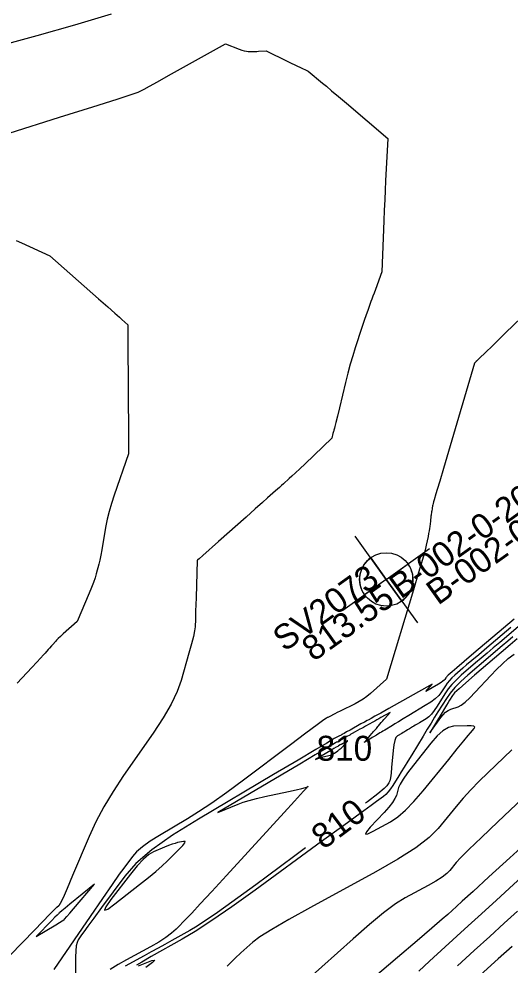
# Model space of a CAD drawing. Extents: x 2079879 to 2092887, y 778083 to 784051.
# Drawn here: x 2084197.8 to 2084253, y 781032.2 to 781138.5 of the extents above; entities that cross this region are included whole.
import ezdxf

# ---------------------------------------------------------------- set-up
doc = ezdxf.new("R2010")
doc.units = 0
for name, color, linetype in [('DT_X_Contour_Major', 7, 'Continuous'), ('DT_X_Contour_Minor', 7, 'Continuous'), ('GT_Project_Soil_Boring', 7, 'Continuous'), ('GT_Project_Text', 7, 'Continuous'), ('SV_X_Text_Comment', 7, 'Continuous'), ('SV_X_Text_Elevation', 7, 'Continuous'), ('SV_X_Text_Name', 7, 'Continuous')]:
    doc.layers.add(name, color=color, linetype=linetype)

msp = doc.modelspace()

# ---------------------------------------------------------------- linework, layer by layer
at = {"layer": 'DT_X_Contour_Major'}
for points in [[(2084197.55, 781113.57), (2084198.15, 781113.29), (2084201.33, 781111.82), (2084206.78, 781107.01), (2084207.82, 781106.09), (2084208.61, 781105.4), (2084209.13, 781104.93), (2084209.41, 781104.69), (2084210.08, 781104.1), (2084210.13, 781094.98), (2084210.14, 781093.24), (2084210.15, 781091.93), (2084210.15, 781091.06), (2084210.15, 781090.63), (2084210.14, 781089.61), (2084208.54, 781084.97), (2084208.23, 781084), (2084207.97, 781083.1), (2084207.76, 781082.27), (2084207.61, 781081.49), (2084207.28, 781079.52), (2084207.16, 781078.82), (2084207.05, 781078.2), (2084206.93, 781077.66), (2084206.82, 781077.21), (2084206.54, 781076.11), (2084206.41, 781075.66), (2084206.24, 781075.15), (2084206.01, 781074.57), (2084205.74, 781073.93), (2084204.38, 781070.77), (2084202.83, 781069.36), (2084202.52, 781069.08), (2084202.27, 781068.84), (2084202.08, 781068.65), (2084201.94, 781068.5), (2084201.64, 781068.16), (2084201.52, 781068.03), (2084201.28, 781067.76), (2084201.15, 781067.61), (2084200.79, 781067.22), (2084200.6, 781067), (2084200.28, 781066.66), (2084199.85, 781066.19), (2084199.29, 781065.6), (2084197.65, 781063.83)], [(2084253.92, 781070.15), (2084251.88, 781068.42), (2084251.14, 781067.79), (2084250.44, 781067.2), (2084249.78, 781066.63), (2084249.16, 781066.1), (2084247.55, 781064.74), (2084246.99, 781064.22), (2084246.49, 781063.7), (2084246.06, 781063.18), (2084245.7, 781062.65), (2084244.82, 781061.24), (2084244.5, 781060.75), (2084244.19, 781060.36), (2084243.89, 781060.05), (2084243.6, 781059.84), (2084242.84, 781059.38), (2084242.58, 781059.23), (2084242.37, 781059.1), (2084242.2, 781059), (2084242.08, 781058.93), (2084241.83, 781058.77), (2084241.74, 781058.72), (2084241.66, 781058.67), (2084241.58, 781058.63), (2084241.52, 781058.59), (2084241.35, 781058.49), (2084241.28, 781058.44), (2084241.17, 781058.38), (2084241.03, 781058.29), (2084240.87, 781058.19), (2084240.38, 781057.9), (2084240.21, 781057.72), (2084240.08, 781057.38), (2084239.97, 781056.89), (2084239.89, 781056.26), (2084239.72, 781054.35), (2084239.65, 781053.71), (2084239.58, 781053.21), (2084239.5, 781052.86), (2084239.42, 781052.65), (2084239.19, 781052.29), (2084238.89, 781052), (2084238.16, 781051.41), (2084237, 781050.51), (2084236.79, 781050.36)], [(2084234.05, 781056.52), (2084234.07, 781056.54), (2084234.1, 781056.57), (2084234.14, 781056.61), (2084234.17, 781056.65), (2084234.47, 781056.99), (2084234.75, 781057.31), (2084234.76, 781057.32), (2084234.76, 781057.32), (2084234.76, 781057.33), (2084234.77, 781057.33), (2084234.77, 781057.34), (2084234.79, 781057.36), (2084234.75, 781057.34), (2084234.73, 781057.33), (2084234.69, 781057.31), (2084234.63, 781057.27), (2084234.56, 781057.23), (2084234.33, 781057.1), (2084234.25, 781057.06), (2084234.19, 781057.03), (2084234.16, 781057.01), (2084234.14, 781057), (2084234.11, 781056.98), (2084234.09, 781056.97), (2084234.06, 781056.95), (2084234.01, 781056.93), (2084233.95, 781056.89), (2084233.77, 781056.79), (2084233.66, 781056.73), (2084233.48, 781056.63), (2084233.23, 781056.48), (2084232.9, 781056.28), (2084231.17, 781055.26), (2084231.6, 781055.44), (2084231.71, 781055.48), (2084231.84, 781055.52), (2084231.99, 781055.56), (2084232.16, 781055.6), (2084232.66, 781055.71), (2084232.84, 781055.75), (2084233.01, 781055.81), (2084233.16, 781055.89), (2084233.3, 781055.98), (2084233.66, 781056.24), (2084233.78, 781056.33), (2084233.87, 781056.4), (2084233.94, 781056.45), (2084233.98, 781056.47), (2084234.05, 781056.52)], [(2084264.54, 781051.3), (2084264.44, 781051.22), (2084263.52, 781050.39), (2084262.27, 781049.26), (2084260.72, 781047.85), (2084258.85, 781046.15), (2084253.43, 781041.22), (2084251.51, 781039.47), (2084249.81, 781037.92), (2084248.33, 781036.56), (2084247.06, 781035.41), (2084243.98, 781032.6), (2084242.76, 781031.5)], [(2084230.06, 781045.33), (2084228.84, 781044.42), (2084227.24, 781043.23), (2084225.77, 781042.16), (2084224.45, 781041.19), (2084221.09, 781038.75), (2084219.9, 781037.9), (2084218.82, 781037.16), (2084217.88, 781036.55), (2084217.05, 781036.06), (2084215.02, 781034.92), (2084214.25, 781034.49), (2084213.48, 781034.07), (2084212.7, 781033.64), (2084211.91, 781033.21), (2084209.8, 781032.06)]]:
    msp.add_lwpolyline(points, dxfattribs=at)
at = {"layer": 'DT_X_Contour_Minor'}
for points in [[(2084188.46, 781133.47), (2084199.89, 781136.6), (2084204.13, 781137.8), (2084208.25, 781139.04)], [(2084191.05, 781123.82), (2084202.42, 781127.4), (2084206.16, 781128.58), (2084208.88, 781129.44), (2084210.57, 781129.99), (2084211.23, 781130.22), (2084211.61, 781130.4), (2084211.91, 781130.55), (2084212.51, 781130.89), (2084213.42, 781131.39), (2084214.64, 781132.08), (2084221.04, 781135.67), (2084222.59, 781135.07), (2084222.9, 781134.95), (2084223.17, 781134.87), (2084223.4, 781134.82), (2084223.59, 781134.8), (2084224.04, 781134.79), (2084224.22, 781134.79), (2084224.39, 781134.79), (2084224.57, 781134.8), (2084224.76, 781134.81), (2084225.64, 781134.86), (2084227.99, 781133.7), (2084228.45, 781133.48), (2084228.84, 781133.29), (2084229.16, 781133.14), (2084229.4, 781133.03), (2084230.34, 781132.6), (2084231.96, 781131.25), (2084232.39, 781130.89), (2084232.98, 781130.39), (2084233.74, 781129.75), (2084234.65, 781128.97), (2084239.3, 781125), (2084239.04, 781120.25), (2084238.99, 781119.2), (2084238.94, 781118.11), (2084238.89, 781116.96), (2084238.84, 781115.76), (2084238.63, 781110.03), (2084237.89, 781108.05), (2084237.74, 781107.65), (2084237.6, 781107.29), (2084237.49, 781106.97), (2084237.39, 781106.7), (2084237.15, 781106.03), (2084237.03, 781105.7), (2084236.87, 781105.22), (2084236.65, 781104.58), (2084236.39, 781103.79), (2084235.63, 781101.49), (2084235.35, 781100.59), (2084235.07, 781099.65), (2084234.81, 781098.66), (2084234.54, 781097.61), (2084233.86, 781094.76), (2084233.63, 781093.82), (2084233.46, 781093.12), (2084233.35, 781092.67), (2084233.3, 781092.47), (2084233.24, 781092.26), (2084233.22, 781092.18), (2084233.19, 781092.09), (2084233.16, 781091.99), (2084233.13, 781091.89), (2084232.99, 781091.37), (2084229.99, 781088.48), (2084229.4, 781087.92), (2084228.91, 781087.45), (2084228.52, 781087.08), (2084228.22, 781086.82), (2084227.58, 781086.24), (2084227.34, 781086.03), (2084227.11, 781085.83), (2084226.89, 781085.63), (2084226.67, 781085.43), (2084225.77, 781084.64), (2084225.2, 781084.13), (2084224.4, 781083.42), (2084223.36, 781082.49), (2084220.26, 781079.74), (2084218.52, 781078.19), (2084218.08, 781077.8), (2084217.93, 781077.67), (2084217.92, 781077.66), (2084217.91, 781077.65), (2084217.91, 781077.65), (2084217.91, 781077.65), (2084217.9, 781077.65), (2084217.9, 781077.64), (2084217.9, 781077.64), (2084217.9, 781077.64), (2084217.89, 781077.64), (2084217.88, 781077.62), (2084217.75, 781073.47), (2084217.72, 781072.65), (2084217.7, 781071.97), (2084217.67, 781071.03), (2084217.64, 781070.16), (2084217.59, 781069.73), (2084217.46, 781069.09), (2084217.25, 781068.24), (2084216.95, 781067.19), (2084216.07, 781064.12), (2084215.62, 781062.89), (2084214.95, 781061.49), (2084214.05, 781059.94), (2084212.92, 781058.23), (2084209.6, 781053.45), (2084208.43, 781051.68), (2084207.39, 781049.95), (2084206.49, 781048.25), (2084205.73, 781046.6), (2084203.88, 781042.23), (2084203.26, 781040.78), (2084202.8, 781039.73), (2084202.49, 781039.08), (2084202.33, 781038.82), (2084202.12, 781038.64), (2084202.05, 781038.59), (2084201.97, 781038.52), (2084201.96, 781038.51), (2084201.96, 781038.51), (2084201.81, 781038.36), (2084201.37, 781037.91), (2084199.6, 781036.1), (2084194.11, 781030.46)], [(2084254.32, 781104.92), (2084252.51, 781103.17), (2084252.05, 781102.72), (2084251.61, 781102.3), (2084251.19, 781101.89), (2084250.1, 781100.84), (2084249.74, 781100.49), (2084249.48, 781100.24), (2084249.32, 781100.08), (2084249.26, 781100.02), (2084249.22, 781099.99), (2084249.21, 781099.98), (2084249.19, 781099.96), (2084249.17, 781099.94), (2084249.15, 781099.91), (2084249.02, 781099.79), (2084246.1, 781089.86), (2084245.54, 781087.96), (2084245.13, 781086.54), (2084244.84, 781085.58), (2084244.7, 781085.1), (2084244.51, 781084.43), (2084244.44, 781084.2), (2084244.39, 781084.01), (2084244.35, 781083.86), (2084244.33, 781083.75), (2084244.29, 781083.51), (2084244.27, 781083.41), (2084244.23, 781083.19), (2084244.21, 781083.07), (2084244.16, 781082.72), (2084244.13, 781082.58), (2084244.11, 781082.42), (2084244.09, 781082.23), (2084244.07, 781082.03), (2084244.01, 781081.44), (2084243.98, 781081.21), (2084243.94, 781080.94), (2084243.88, 781080.64), (2084243.81, 781080.3), (2084243.61, 781079.35), (2084243.47, 781078.77), (2084243.18, 781077.74), (2084242.74, 781076.26), (2084242.17, 781074.33), (2084239.15, 781064.28), (2084237.34, 781062.68), (2084236.94, 781062.35), (2084236.53, 781062.04), (2084236.09, 781061.77), (2084235.63, 781061.52), (2084233.95, 781060.69), (2084233.61, 781060.52), (2084233.35, 781060.39), (2084233.18, 781060.31), (2084232.84, 781060.14), (2084232.62, 781060.03), (2084232.55, 781059.99), (2084232.5, 781059.97), (2084232.39, 781059.91), (2084232.1, 781059.71), (2084231.34, 781059.14), (2084230.08, 781058.2), (2084228.35, 781056.9), (2084223.07, 781052.94), (2084221.19, 781051.55), (2084219.52, 781050.36), (2084218.04, 781049.37), (2084216.77, 781048.58), (2084213.65, 781046.74), (2084212.58, 781046.07), (2084211.72, 781045.46), (2084211.05, 781044.89), (2084210.59, 781044.38), (2084209.63, 781043.07), (2084209.12, 781042.36), (2084208.32, 781041.22), (2084207.23, 781039.64), (2084205.85, 781037.63), (2084201.77, 781031.68)], [(2084253.49, 781071.03), (2084252.29, 781070.02), (2084248.96, 781067.19), (2084247.86, 781066.26), (2084247.05, 781065.57), (2084246.53, 781065.12), (2084246.3, 781064.93), (2084246.08, 781064.74), (2084246, 781064.67), (2084245.93, 781064.59), (2084245.87, 781064.52), (2084245.82, 781064.45), (2084245.69, 781064.25), (2084245.62, 781064.16), (2084245.47, 781064.05), (2084245.27, 781063.91), (2084244.99, 781063.74), (2084243.58, 781062.88), (2084244.29, 781063.71), (2084239.41, 781060.99), (2084238.49, 781060.48), (2084237.83, 781060.11), (2084237.42, 781059.88), (2084237.28, 781059.8), (2084237.22, 781059.77), (2084237.15, 781059.73), (2084236.97, 781059.63), (2084236.68, 781059.47), (2084236.27, 781059.25), (2084235.06, 781058.57), (2084234.66, 781058.35), (2084234.38, 781058.19), (2084234.2, 781058.09), (2084234.15, 781058.06), (2084234.14, 781058.06), (2084234.14, 781058.06), (2084234.14, 781058.06), (2084234.14, 781058.06), (2084234.14, 781058.06), (2084234.14, 781058.06), (2084234.13, 781058.05), (2084234.11, 781058.04), (2084234.08, 781058.02), (2084234.04, 781058), (2084233.8, 781057.87), (2084233.27, 781057.61), (2084233.17, 781057.55), (2084233.08, 781057.51), (2084233.01, 781057.47), (2084232.97, 781057.43), (2084232.86, 781057.36), (2084232.43, 781057.1), (2084231.22, 781056.38), (2084229.23, 781055.2), (2084226.45, 781053.56), (2084218.01, 781048.57), (2084215.12, 781046.77), (2084212.77, 781045.1), (2084210.98, 781043.57), (2084209.73, 781042.17), (2084207.12, 781038.63), (2084206.25, 781037.44), (2084205.59, 781036.53), (2084205.13, 781035.91), (2084204.89, 781035.56), (2084204.51, 781035), (2084204.38, 781034.72), (2084204.29, 781034.31), (2084204.23, 781033.75), (2084204.21, 781033.05), (2084204.2, 781031)], [(2084253.1, 781070.08), (2084250.42, 781067.81), (2084249.5, 781067.02), (2084248.74, 781066.38), (2084248.15, 781065.88), (2084247.73, 781065.52), (2084246.82, 781064.74), (2084246.49, 781064.44), (2084246.21, 781064.15), (2084245.96, 781063.85), (2084245.76, 781063.55), (2084245.26, 781062.74), (2084245.01, 781062.43), (2084244.63, 781062.08), (2084244.13, 781061.71), (2084243.5, 781061.31), (2084241.65, 781060.19), (2084241.01, 781059.81), (2084240.49, 781059.5), (2084240.09, 781059.25), (2084239.8, 781059.08), (2084238.95, 781058.57), (2084238.75, 781058.45), (2084238.57, 781058.34), (2084238.41, 781058.24), (2084238.01, 781058), (2084237.7, 781057.82), (2084237.54, 781057.72), (2084237.38, 781057.63), (2084236.63, 781057.17), (2084236.96, 781057.56), (2084237.07, 781057.69), (2084237.11, 781057.73), (2084237.13, 781057.75), (2084237.16, 781057.79), (2084237.18, 781057.81), (2084237.26, 781057.9), (2084237.32, 781057.97), (2084237.5, 781058.18), (2084237.57, 781058.26), (2084237.64, 781058.35), (2084237.8, 781058.52), (2084238.01, 781058.76), (2084238.09, 781058.86), (2084238.17, 781058.95), (2084238.25, 781059.04), (2084238.56, 781059.4), (2084238.65, 781059.51), (2084238.75, 781059.62), (2084238.86, 781059.75), (2084238.97, 781059.88), (2084239.54, 781060.54), (2084238.5, 781059.96), (2084238.28, 781059.83), (2084238.05, 781059.71), (2084237.83, 781059.58), (2084237.6, 781059.45), (2084236.77, 781058.99), (2084236.56, 781058.87), (2084236.35, 781058.76), (2084236.16, 781058.65), (2084235.64, 781058.36), (2084235.29, 781058.17), (2084235.14, 781058.09), (2084235.01, 781058.01), (2084234.68, 781057.83), (2084234.57, 781057.77), (2084234.4, 781057.67), (2084234.35, 781057.64), (2084234.23, 781057.58), (2084234.19, 781057.55), (2084234.13, 781057.52), (2084233.97, 781057.44), (2084233.74, 781057.31), (2084233.66, 781057.26), (2084233.59, 781057.22), (2084233.54, 781057.2), (2084233.41, 781057.12), (2084233.13, 781056.96), (2084232.37, 781056.51), (2084231.13, 781055.77), (2084229.4, 781054.75), (2084220.2, 781049.29), (2084222.49, 781050.25), (2084223.05, 781050.46), (2084223.73, 781050.67), (2084224.54, 781050.88), (2084225.47, 781051.09), (2084228.13, 781051.67), (2084229.01, 781051.86), (2084229.65, 781052.01), (2084230.04, 781052.1), (2084230.2, 781052.15), (2084230.35, 781052.27), (2084230.2, 781052.1), (2084230.15, 781052.05), (2084230.1, 781051.99), (2084230.03, 781051.91), (2084229.82, 781051.69), (2084228.8, 781050.57), (2084227.63, 781049.29), (2084226.03, 781047.54), (2084221.17, 781042.24), (2084219.52, 781040.44), (2084218.22, 781039.04), (2084217.26, 781038.01), (2084216.66, 781037.38), (2084215.5, 781036.2), (2084215, 781035.74), (2084214.35, 781035.26), (2084213.56, 781034.75), (2084212.63, 781034.22), (2084209.95, 781032.76), (2084208.98, 781032.22), (2084208.1, 781031.68)], [(2084253.34, 781069.04), (2084252.78, 781068.56), (2084252.13, 781068.01), (2084251.4, 781067.39), (2084250.58, 781066.69), (2084248.29, 781064.73), (2084247.5, 781064.02), (2084246.83, 781063.35), (2084246.28, 781062.72), (2084245.87, 781062.13), (2084244.92, 781060.6), (2084244.55, 781060), (2084244.15, 781059.35), (2084243.72, 781058.65), (2084243.26, 781057.89), (2084241.98, 781055.79), (2084241.53, 781055.06), (2084241.14, 781054.41), (2084240.81, 781053.86), (2084240.53, 781053.41), (2084239.86, 781052.33), (2084239.61, 781051.95), (2084239.35, 781051.62), (2084239.07, 781051.33), (2084238.79, 781051.1), (2084238.03, 781050.53), (2084237.43, 781050.09), (2084236.2, 781049.19), (2084234.34, 781047.84), (2084231.85, 781046.03), (2084224.38, 781040.59), (2084221.76, 781038.72), (2084219.52, 781037.17), (2084217.66, 781035.95), (2084216.17, 781035.06), (2084212.72, 781033.12), (2084211.65, 781032.51), (2084211.06, 781032.14)], [(2084253.83, 781068.83), (2084253.03, 781068.14), (2084252.01, 781067.28), (2084249.03, 781064.73), (2084248.04, 781063.87), (2084247.3, 781063.2), (2084246.8, 781062.73), (2084246.55, 781062.44), (2084246.23, 781061.91), (2084246.09, 781061.68), (2084245.9, 781061.38), (2084245.67, 781061), (2084245.39, 781060.54), (2084244, 781058.25), (2084245.24, 781059.96), (2084245.51, 781060.29), (2084245.79, 781060.56), (2084246.08, 781060.77), (2084246.38, 781060.9), (2084247.19, 781061.18), (2084247.53, 781061.36), (2084247.97, 781061.69), (2084248.49, 781062.18), (2084249.1, 781062.81), (2084250.85, 781064.7), (2084251.5, 781065.38), (2084252.16, 781066.01), (2084252.82, 781066.59), (2084253.48, 781067.11)], [(2084239.61, 781048.27), (2084240.4, 781048.8), (2084241.27, 781049.55), (2084242.22, 781050.53), (2084243.26, 781051.74), (2084246.14, 781055.27), (2084247.1, 781056.45), (2084247.83, 781057.34), (2084248.33, 781057.95), (2084248.6, 781058.27), (2084249.01, 781058.75), (2084249.07, 781058.9), (2084248.96, 781059), (2084248.66, 781059.05), (2084248.19, 781059.05), (2084246.69, 781058.99), (2084246.11, 781058.85), (2084245.48, 781058.49), (2084244.82, 781057.9), (2084244.11, 781057.09), (2084242.17, 781054.61), (2084241.52, 781053.76), (2084241.03, 781053.05), (2084240.69, 781052.5), (2084240.51, 781052.1), (2084240.25, 781051.23), (2084240.09, 781050.87), (2084239.81, 781050.43), (2084239.4, 781049.91), (2084238.87, 781049.32), (2084237.31, 781047.64), (2084236.89, 781047.14), (2084236.8, 781046.89), (2084237.05, 781046.91), (2084237.63, 781047.19), (2084239.61, 781048.27)], [(2084253.24, 781056.35), (2084250.52, 781053.77), (2084249.54, 781052.81), (2084248.61, 781051.86), (2084247.76, 781050.91), (2084246.96, 781049.97), (2084244.94, 781047.49), (2084243.93, 781046.48), (2084242.43, 781045.34), (2084240.43, 781044.05), (2084237.93, 781042.63), (2084230.62, 781038.64), (2084228.16, 781037.27), (2084226.26, 781036.17), (2084224.91, 781035.32), (2084224.13, 781034.74), (2084222.78, 781033.53), (2084222.14, 781032.93), (2084221.25, 781032.04)], [(2084257.15, 781053.48), (2084251.64, 781048.25), (2084249.8, 781046.49), (2084248.41, 781045.15), (2084247.46, 781044.21), (2084246.97, 781043.68), (2084246.26, 781042.8), (2084245.91, 781042.45), (2084245.38, 781042.05), (2084244.68, 781041.6), (2084243.81, 781041.1), (2084241.25, 781039.71), (2084240.16, 781039.03), (2084238.82, 781038.04), (2084237.23, 781036.74), (2084235.39, 781035.12), (2084230.13, 781030.41)], [(2084260.01, 781050.59), (2084252.99, 781044.2), (2084250.65, 781042.06), (2084248.87, 781040.44), (2084247.65, 781039.34), (2084247, 781038.75), (2084246.03, 781037.86), (2084245.4, 781037.31), (2084244.25, 781036.32), (2084242.58, 781034.89), (2084240.38, 781033.02), (2084233.83, 781027.45)], [(2084215.67, 781045.92), (2084215.39, 781045.84), (2084215.05, 781045.73), (2084214.66, 781045.59), (2084214.21, 781045.41), (2084212.95, 781044.88), (2084212.43, 781044.58), (2084211.83, 781044.06), (2084211.14, 781043.32), (2084210.37, 781042.36), (2084208.19, 781039.53), (2084207.6, 781038.7), (2084207.48, 781038.34), (2084207.83, 781038.46), (2084208.64, 781039.04), (2084211.41, 781041.22), (2084212.39, 781041.99), (2084213.23, 781042.69), (2084213.93, 781043.31), (2084214.51, 781043.85), (2084215.85, 781045.18), (2084216.26, 781045.61), (2084216.48, 781045.9), (2084216.51, 781046.05), (2084216.35, 781046.06), (2084215.67, 781045.92)], [(2084202.01, 781036.7), (2084202.42, 781036.95), (2084202.72, 781037.13), (2084202.9, 781037.24), (2084202.97, 781037.29), (2084202.98, 781037.31), (2084203.24, 781037.61), (2084203.56, 781037.98), (2084203.99, 781038.5), (2084206.32, 781041.25), (2084203.57, 781038.99), (2084203.05, 781038.57), (2084202.68, 781038.26), (2084202.45, 781038.07), (2084202.36, 781038), (2084202.33, 781037.98), (2084202.28, 781037.92), (2084202.13, 781037.77), (2084201.89, 781037.53), (2084201.56, 781037.19), (2084199.8, 781035.38), (2084202.01, 781036.7)], [(2084253.87, 781038.23), (2084252.38, 781036.87), (2084250.76, 781035.39), (2084249, 781033.79), (2084247.12, 781032.08)], [(2084253.25, 781034.27), (2084251.7, 781032.86), (2084249.68, 781031.02)], [(2084211.27, 781032.09), (2084212.79, 781032.67), (2084213.1, 781032.72), (2084212.87, 781032.46), (2084212.12, 781031.88)]]:
    msp.add_lwpolyline(points, dxfattribs=at)
at = {"layer": 'GT_Project_Soil_Boring'}
for p, q in [((2084239.12, 781075.49), (2084235.62, 781080.36)), ((2084239.12, 781075.49), (2084243.99, 781078.98)), ((2084237.37, 781077.92), (2084239.12, 781075.49)), ((2084239.12, 781075.49), (2084241.56, 781077.23)), ((2084239.12, 781075.49), (2084234.24, 781071.99)), ((2084239.12, 781075.49), (2084236.68, 781073.74)), ((2084239.12, 781075.49), (2084242.61, 781070.61)), ((2084240.86, 781073.05), (2084239.12, 781075.49))]:
    msp.add_line(p, q, dxfattribs=at)
msp.add_circle((2084239.12, 781075.49), 3, dxfattribs=at)
for start, end in [(125.6254, 215.6254), (305.6254, 35.6254)]:
    msp.add_arc((2084239.12, 781075.49), 3, start, end, dxfattribs=at)

# ---------------------------------------------------------------- texts
at = {"layer": 'DT_X_Contour_Major'}
msp.add_text('810', height=2.8, dxfattribs=at).set_placement((2084231.29, 781055.12))
msp.add_text('810', height=2.8, rotation=36.7586, dxfattribs=at).set_placement((2084232.06, 781045.07))
at = {"layer": 'GT_Project_Text'}
msp.add_text('B-002-0-20', height=2.8, rotation=35.6254, dxfattribs=at).set_placement((2084244.93, 781072.52))
at = {"layer": 'SV_X_Text_Comment'}
msp.add_text('B-002-0-20', height=2.8, rotation=35.6254, dxfattribs=at).set_placement((2084240.75, 781073.21))
at = {"layer": 'SV_X_Text_Elevation'}
msp.add_text('813.55', height=2.8, rotation=35.6254, dxfattribs=at).set_placement((2084230.95, 781066.19))
at = {"layer": 'SV_X_Text_Name'}
msp.add_text('SV2073', height=2.8, rotation=35.6254, dxfattribs=at).set_placement((2084227.68, 781067.29))

doc.saveas('drawing.dxf')
